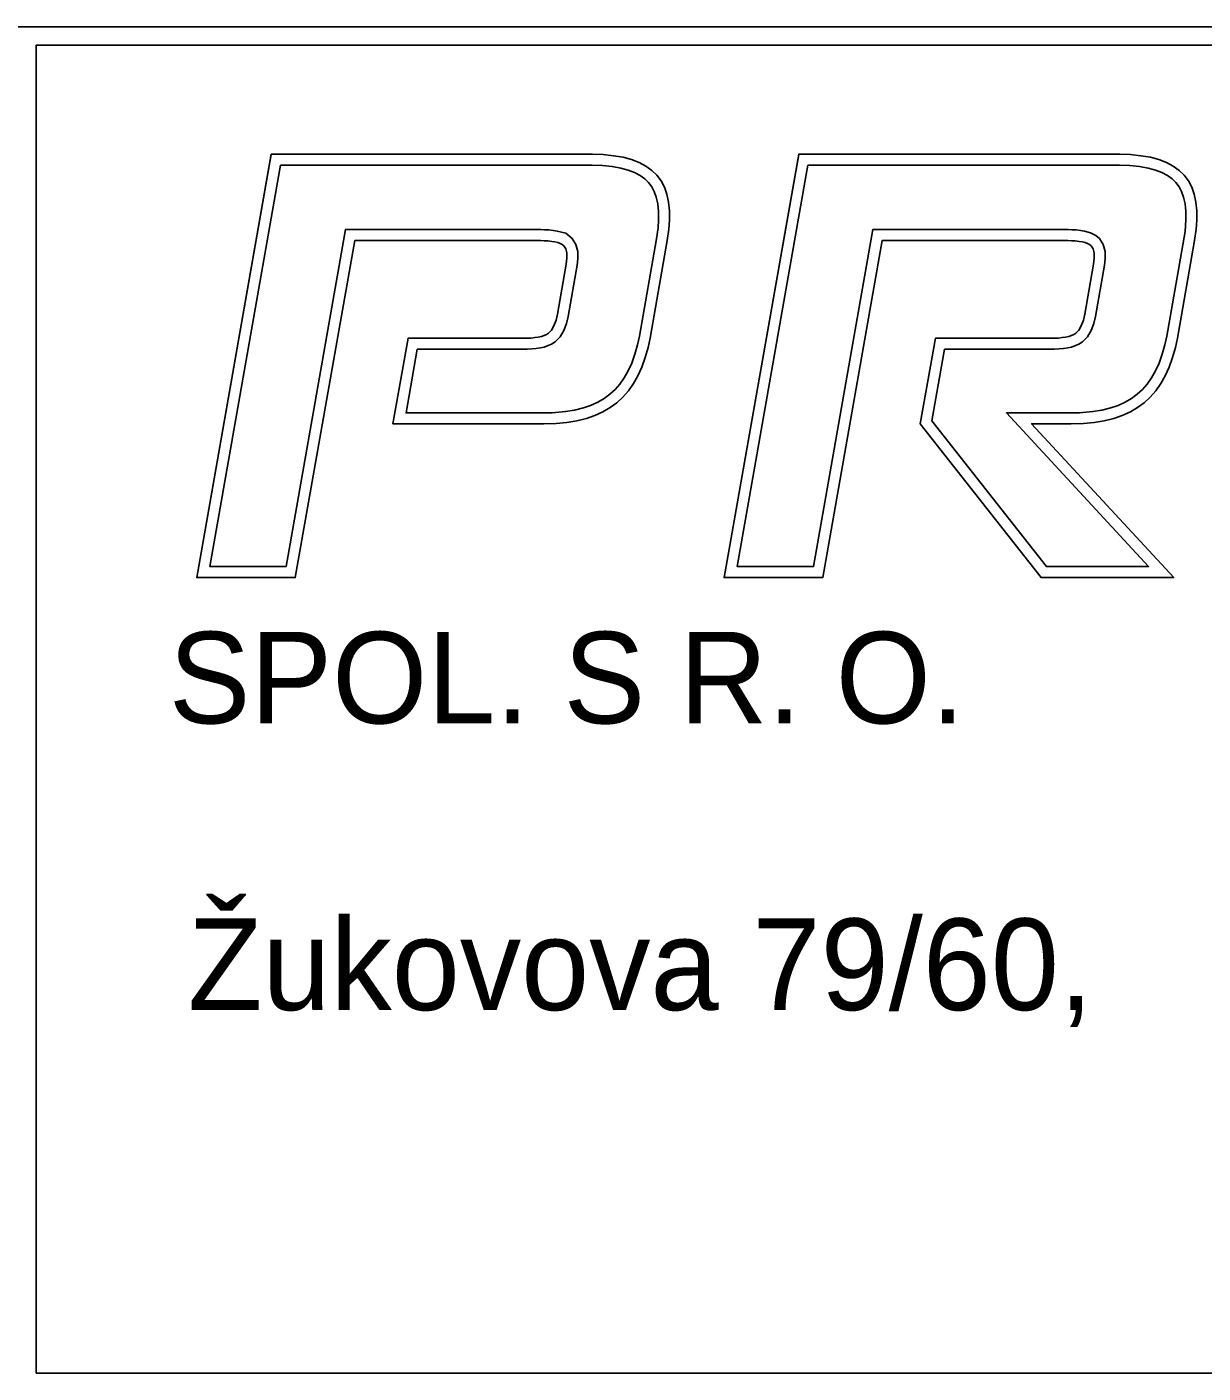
# Model space of a CAD drawing. Extents: x 377 to 692, y 94 to 238.
# Drawn here: x 660.63 to 672.83, y 115.77 to 129.74 of the extents above; entities that cross this region are included whole.
import ezdxf

# ---------------------------------------------------------------- set-up
doc = ezdxf.new("R2010")
doc.units = 0
doc.layers.add('000_rozpiska', color=7, linetype='Continuous')

msp = doc.modelspace()

# ---------------------------------------------------------------- linework, layer by layer
at = {"layer": '000_rozpiska'}
for p, q in [((687.796, 129.736), (601.346, 129.736)), ((687.796, 129.736), (601.346, 129.736)), ((687.796, 129.546), (660.721, 129.546)), ((660.721, 115.77), (660.721, 129.546)), ((662.389, 124.023), (663.162, 128.413)), ((663.161, 128.414), (666.493, 128.414)), ((667.86, 124.023), (668.633, 128.413)), ((668.632, 128.414), (671.964, 128.414)), ((664.027, 127.519), (663.411, 124.023)), ((664.027, 127.519), (665.955, 127.519)), ((667.27, 127.519), (667.091, 126.506)), ((669.498, 127.519), (668.882, 124.023)), ((669.498, 127.519), (671.426, 127.519)), ((672.741, 127.519), (672.562, 126.506)), ((666.222, 127.276), (666.131, 126.755)), ((671.693, 127.276), (671.602, 126.755)), ((664.581, 126.506), (664.424, 125.618)), ((664.581, 126.506), (665.777, 126.506)), ((670.052, 126.506), (669.895, 125.618)), ((670.052, 126.506), (671.248, 126.506)), ((664.424, 125.618), (665.989, 125.618)), ((671.148, 124.023), (669.895, 125.618)), ((671.049, 125.618), (671.46, 125.618)), ((672.524, 124.023), (671.049, 125.618)), ((663.411, 124.023), (662.389, 124.023)), ((668.882, 124.023), (667.86, 124.023)), ((672.524, 124.023), (671.148, 124.023)), ((689.031, 115.77), (660.721, 115.77))]:
    msp.add_line(p, q, dxfattribs=at)
for points in [[(660.721, 115.77), (660.721, 129.546), (687.796, 129.546)], [(666.9, 128.359), (666.811, 128.383), (666.713, 128.4), (666.606, 128.411), (666.493, 128.414), (663.162, 128.414), (662.389, 124.023), (663.411, 124.023), (664.027, 127.519), (665.955, 127.519), (665.991, 127.518), (666.032, 127.516), (666.072, 127.511), (666.105, 127.506), (666.135, 127.498), (666.159, 127.489), (666.18, 127.478), (666.196, 127.465), (666.216, 127.433), (666.227, 127.391), (666.229, 127.336), (666.222, 127.276), (666.131, 126.755), (666.116, 126.692), (666.094, 126.635), (666.068, 126.591), (666.036, 126.558), (666.016, 126.546), (665.992, 126.535), (665.964, 126.525), (665.932, 126.518), (665.895, 126.512), (665.857, 126.508), (665.812, 126.506), (665.777, 126.506), (664.581, 126.506), (664.424, 125.618), (665.989, 125.618), (666.116, 125.622), (666.229, 125.632), (666.33, 125.649), (666.432, 125.674), (666.517, 125.703), (666.603, 125.742), (666.677, 125.786), (666.745, 125.835), (666.81, 125.894), (666.867, 125.961), (666.919, 126.035), (666.965, 126.116), (667.006, 126.206), (667.042, 126.306), (667.071, 126.409), (667.091, 126.506), (667.27, 127.519), (667.287, 127.638), (667.294, 127.73), (667.292, 127.829), (667.284, 127.917), (667.266, 128), (667.24, 128.072), (667.206, 128.139), (667.162, 128.197), (667.11, 128.247), (667.049, 128.291), (666.978, 128.329), (666.9, 128.359)], [(666.493, 128.414), (666.606, 128.411), (666.713, 128.4), (666.811, 128.383), (666.9, 128.359), (666.978, 128.329), (667.049, 128.291), (667.11, 128.247), (667.162, 128.197), (667.206, 128.139), (667.24, 128.072), (667.266, 128), (667.284, 127.917), (667.292, 127.829), (667.294, 127.73), (667.287, 127.638), (667.27, 127.519)], [(672.758, 127.638), (672.765, 127.73), (672.763, 127.829), (672.755, 127.917), (672.736, 128), (672.711, 128.072), (672.677, 128.139), (672.633, 128.197), (672.581, 128.247), (672.52, 128.291), (672.449, 128.329), (672.371, 128.359), (672.282, 128.383), (672.184, 128.4), (672.077, 128.411), (671.964, 128.414), (668.633, 128.414), (667.86, 124.023), (668.882, 124.023), (669.498, 127.519), (671.426, 127.519), (671.462, 127.518), (671.503, 127.516), (671.543, 127.511), (671.576, 127.506), (671.606, 127.498), (671.63, 127.489), (671.651, 127.478), (671.667, 127.465), (671.687, 127.433), (671.698, 127.391), (671.7, 127.336), (671.693, 127.276), (671.602, 126.755), (671.587, 126.692), (671.565, 126.635), (671.539, 126.591), (671.507, 126.558), (671.487, 126.546), (671.463, 126.535), (671.435, 126.525), (671.403, 126.518), (671.366, 126.512), (671.328, 126.508), (671.283, 126.506), (671.248, 126.506), (670.052, 126.506), (669.895, 125.618), (671.148, 124.023), (672.524, 124.023), (671.049, 125.618), (671.46, 125.618), (671.587, 125.622), (671.7, 125.632), (671.801, 125.649), (671.903, 125.674), (671.988, 125.703), (672.074, 125.742), (672.148, 125.786), (672.216, 125.835), (672.281, 125.894), (672.338, 125.961), (672.39, 126.035), (672.436, 126.116), (672.477, 126.206), (672.513, 126.306), (672.542, 126.409), (672.562, 126.506), (672.741, 127.519), (672.758, 127.638)], [(671.964, 128.414), (672.077, 128.411), (672.184, 128.4), (672.282, 128.383), (672.371, 128.359), (672.449, 128.329), (672.52, 128.291), (672.581, 128.247), (672.633, 128.197), (672.677, 128.139), (672.711, 128.072), (672.736, 128), (672.755, 127.917), (672.763, 127.829), (672.765, 127.73), (672.758, 127.638), (672.741, 127.519)], [(689.031, 128.311), (689.031, 115.77), (660.721, 115.77)], [(663.258, 128.3), (666.49, 128.3), (666.599, 128.297), (666.698, 128.287), (666.787, 128.272), (666.864, 128.251), (666.93, 128.225), (666.989, 128.194), (667.036, 128.16), (667.076, 128.121), (667.109, 128.078), (667.135, 128.027), (667.156, 127.968), (667.171, 127.9), (667.178, 127.823), (667.18, 127.733), (667.174, 127.65), (667.157, 127.537), (666.98, 126.529), (666.96, 126.436), (666.934, 126.34), (666.901, 126.249), (666.864, 126.168), (666.823, 126.096), (666.777, 126.031), (666.728, 125.974), (666.673, 125.924), (666.615, 125.881), (666.55, 125.844), (666.475, 125.809), (666.4, 125.784), (666.307, 125.761), (666.214, 125.745), (666.076, 125.732), (664.56, 125.732), (664.676, 126.392), (665.779, 126.392), (665.816, 126.392), (665.866, 126.395), (665.909, 126.399), (665.953, 126.406), (665.994, 126.415), (666.035, 126.429), (666.07, 126.445), (666.107, 126.468), (666.159, 126.521), (666.198, 126.586), (666.225, 126.659), (666.242, 126.733), (666.335, 127.263), (666.343, 127.331), (666.341, 127.407), (666.322, 127.48), (666.282, 127.542), (666.217, 127.595), (666.129, 127.617), (666.087, 127.624), (666.041, 127.629), (665.995, 127.632), (665.958, 127.633), (663.931, 127.633), (663.315, 124.137), (662.525, 124.137), (663.258, 128.3)], [(667.171, 127.9), (667.156, 127.968), (667.135, 128.027), (667.109, 128.078), (667.076, 128.121), (667.036, 128.16), (666.989, 128.194), (666.93, 128.225), (666.864, 128.251), (666.787, 128.272), (666.698, 128.287), (666.599, 128.297), (666.49, 128.3), (663.258, 128.3), (662.525, 124.137), (663.315, 124.137), (663.931, 127.633), (665.958, 127.633), (665.995, 127.632), (666.041, 127.629), (666.087, 127.624), (666.129, 127.617), (666.217, 127.595), (666.282, 127.542), (666.322, 127.48), (666.341, 127.407), (666.343, 127.331), (666.335, 127.263), (666.242, 126.733), (666.225, 126.659), (666.198, 126.586), (666.159, 126.521), (666.107, 126.468), (666.07, 126.445), (666.035, 126.429), (665.994, 126.415), (665.953, 126.406), (665.909, 126.399), (665.866, 126.395), (665.816, 126.392), (665.779, 126.392), (664.676, 126.392), (664.56, 125.732), (666.076, 125.732), (666.214, 125.745), (666.307, 125.761), (666.4, 125.784), (666.475, 125.809), (666.55, 125.844), (666.615, 125.881), (666.673, 125.924), (666.728, 125.974), (666.777, 126.031), (666.823, 126.096), (666.864, 126.168), (666.901, 126.249), (666.934, 126.34), (666.96, 126.436), (666.98, 126.529), (667.157, 127.537), (667.174, 127.65), (667.18, 127.733), (667.178, 127.823), (667.171, 127.9)], [(663.931, 127.633), (663.315, 124.137), (662.525, 124.137), (663.258, 128.3), (666.49, 128.3), (666.599, 128.297), (666.698, 128.287), (666.787, 128.272), (666.864, 128.251), (666.93, 128.225), (666.989, 128.194), (667.036, 128.16), (667.076, 128.121), (667.109, 128.078), (667.135, 128.027), (667.156, 127.968), (667.171, 127.9), (667.178, 127.823), (667.18, 127.733), (667.174, 127.65), (667.157, 127.537), (666.98, 126.529), (666.96, 126.436), (666.934, 126.34), (666.901, 126.249), (666.864, 126.168), (666.823, 126.096), (666.777, 126.031), (666.728, 125.974), (666.673, 125.924), (666.615, 125.881), (666.55, 125.844), (666.475, 125.809), (666.4, 125.784), (666.307, 125.761), (666.214, 125.745), (666.076, 125.732), (664.56, 125.732), (664.676, 126.392), (665.779, 126.392), (665.816, 126.392), (665.866, 126.395), (665.909, 126.399), (665.953, 126.406), (665.994, 126.415), (666.035, 126.429), (666.07, 126.445), (666.107, 126.468), (666.159, 126.521), (666.198, 126.586), (666.225, 126.659), (666.242, 126.733), (666.335, 127.263), (666.343, 127.331), (666.341, 127.407), (666.322, 127.48), (666.282, 127.542), (666.217, 127.595), (666.129, 127.617), (666.087, 127.624), (666.041, 127.629), (665.995, 127.632), (665.958, 127.633), (663.931, 127.633)], [(669.402, 127.633), (668.786, 124.137), (667.996, 124.137), (668.729, 128.3), (671.961, 128.3), (672.07, 128.297), (672.169, 128.287), (672.258, 128.272), (672.335, 128.251), (672.401, 128.225), (672.46, 128.194), (672.507, 128.16), (672.547, 128.121), (672.58, 128.078), (672.606, 128.027), (672.627, 127.968), (672.642, 127.9), (672.649, 127.823), (672.651, 127.733), (672.642, 127.614), (672.451, 126.529), (672.431, 126.436), (672.405, 126.34), (672.372, 126.249), (672.335, 126.168), (672.294, 126.096), (672.248, 126.031), (672.199, 125.974), (672.144, 125.924), (672.086, 125.881), (672.021, 125.844), (671.946, 125.809), (671.871, 125.784), (671.778, 125.761), (671.685, 125.745), (671.547, 125.732), (670.788, 125.732), (672.263, 124.137), (671.204, 124.137), (670.016, 125.649), (670.147, 126.392), (671.25, 126.392), (671.287, 126.392), (671.337, 126.395), (671.38, 126.399), (671.424, 126.406), (671.465, 126.415), (671.506, 126.429), (671.541, 126.445), (671.578, 126.468), (671.63, 126.521), (671.669, 126.586), (671.696, 126.659), (671.713, 126.733), (671.806, 127.263), (671.814, 127.331), (671.812, 127.407), (671.793, 127.48), (671.753, 127.542), (671.715, 127.573), (671.662, 127.601), (671.6, 127.617), (671.558, 127.624), (671.512, 127.629), (671.466, 127.632), (671.429, 127.633), (669.402, 127.633)], [(672.606, 128.027), (672.58, 128.078), (672.547, 128.121), (672.507, 128.16), (672.46, 128.194), (672.401, 128.225), (672.335, 128.251), (672.258, 128.272), (672.169, 128.287), (672.07, 128.297), (671.961, 128.3), (668.729, 128.3), (667.996, 124.137), (668.786, 124.137), (669.402, 127.633), (671.429, 127.633), (671.466, 127.632), (671.512, 127.629), (671.558, 127.624), (671.6, 127.617), (671.662, 127.601), (671.715, 127.573), (671.753, 127.542), (671.793, 127.48), (671.812, 127.407), (671.814, 127.331), (671.806, 127.263), (671.713, 126.733), (671.696, 126.659), (671.669, 126.586), (671.63, 126.521), (671.578, 126.468), (671.541, 126.445), (671.506, 126.429), (671.465, 126.415), (671.424, 126.406), (671.38, 126.399), (671.337, 126.395), (671.287, 126.392), (671.25, 126.392), (670.147, 126.392), (670.016, 125.649), (671.204, 124.137), (672.263, 124.137), (670.788, 125.732), (671.547, 125.732), (671.685, 125.745), (671.778, 125.761), (671.871, 125.784), (671.946, 125.809), (672.021, 125.844), (672.086, 125.881), (672.144, 125.924), (672.199, 125.974), (672.248, 126.031), (672.294, 126.096), (672.335, 126.168), (672.372, 126.249), (672.405, 126.34), (672.431, 126.436), (672.451, 126.529), (672.642, 127.614), (672.651, 127.733), (672.649, 127.823), (672.642, 127.9), (672.627, 127.968), (672.606, 128.027)], [(669.402, 127.633), (668.786, 124.137), (667.996, 124.137), (668.729, 128.3), (671.961, 128.3), (672.07, 128.297), (672.169, 128.287), (672.258, 128.272), (672.335, 128.251), (672.401, 128.225), (672.46, 128.194), (672.507, 128.16), (672.547, 128.121), (672.58, 128.078), (672.606, 128.027), (672.627, 127.968), (672.642, 127.9), (672.649, 127.823), (672.651, 127.733), (672.642, 127.614), (672.451, 126.529), (672.431, 126.436), (672.405, 126.34), (672.372, 126.249), (672.335, 126.168), (672.294, 126.096), (672.248, 126.031), (672.199, 125.974), (672.144, 125.924), (672.086, 125.881), (672.021, 125.844), (671.946, 125.809), (671.871, 125.784), (671.778, 125.761), (671.685, 125.745), (671.547, 125.732), (670.788, 125.732), (672.263, 124.137), (671.204, 124.137), (670.016, 125.649), (670.147, 126.392), (671.25, 126.392), (671.287, 126.392), (671.337, 126.395), (671.38, 126.399), (671.424, 126.406), (671.465, 126.415), (671.506, 126.429), (671.541, 126.445), (671.578, 126.468), (671.63, 126.521), (671.669, 126.586), (671.696, 126.659), (671.713, 126.733), (671.806, 127.263), (671.814, 127.331), (671.812, 127.407), (671.793, 127.48), (671.753, 127.542), (671.715, 127.573), (671.662, 127.601), (671.6, 127.617), (671.558, 127.624), (671.512, 127.629), (671.466, 127.632), (671.429, 127.633), (669.402, 127.633)], [(666.135, 127.498), (666.105, 127.506), (666.072, 127.511), (666.032, 127.516), (665.991, 127.518), (665.955, 127.519)], [(671.606, 127.498), (671.576, 127.506), (671.543, 127.511), (671.503, 127.516), (671.462, 127.518), (671.426, 127.519)], [(666.222, 127.276), (666.229, 127.336), (666.227, 127.391), (666.216, 127.433), (666.196, 127.465), (666.18, 127.478), (666.159, 127.489), (666.135, 127.498)], [(671.693, 127.276), (671.7, 127.336), (671.698, 127.391), (671.687, 127.433), (671.667, 127.465), (671.651, 127.478), (671.63, 127.489), (671.606, 127.498)], [(666.131, 126.755), (666.116, 126.692), (666.094, 126.635), (666.068, 126.591), (666.036, 126.558), (666.016, 126.546), (665.992, 126.535), (665.964, 126.525), (665.932, 126.518), (665.895, 126.512), (665.857, 126.508), (665.812, 126.506), (665.777, 126.506)], [(671.602, 126.755), (671.587, 126.692), (671.565, 126.635), (671.539, 126.591), (671.507, 126.558), (671.487, 126.546), (671.463, 126.535), (671.435, 126.525), (671.403, 126.518), (671.366, 126.512), (671.328, 126.508), (671.283, 126.506), (671.248, 126.506)], [(667.091, 126.506), (667.071, 126.409), (667.042, 126.306), (667.006, 126.206), (666.965, 126.116), (666.919, 126.035), (666.867, 125.961), (666.81, 125.894), (666.745, 125.835), (666.677, 125.786), (666.603, 125.742), (666.517, 125.703), (666.432, 125.674), (666.33, 125.649), (666.229, 125.632), (666.116, 125.622), (665.989, 125.618)], [(672.562, 126.506), (672.542, 126.409), (672.513, 126.306), (672.477, 126.206), (672.436, 126.116), (672.39, 126.035), (672.338, 125.961), (672.281, 125.894), (672.216, 125.835), (672.148, 125.786), (672.074, 125.742), (671.988, 125.703), (671.903, 125.674), (671.801, 125.649), (671.7, 125.632), (671.587, 125.622), (671.46, 125.618)]]:
    msp.add_lwpolyline(points, dxfattribs=at)

# ---------------------------------------------------------------- texts
for s, p in [('SPOL. S R. O.', (662.098, 122.51)), ('Žukovova 79/60, ', (662.294, 119.536))]:
    msp.add_text(s, height=0.95, dxfattribs=at).set_placement(p)

doc.saveas('drawing.dxf')
